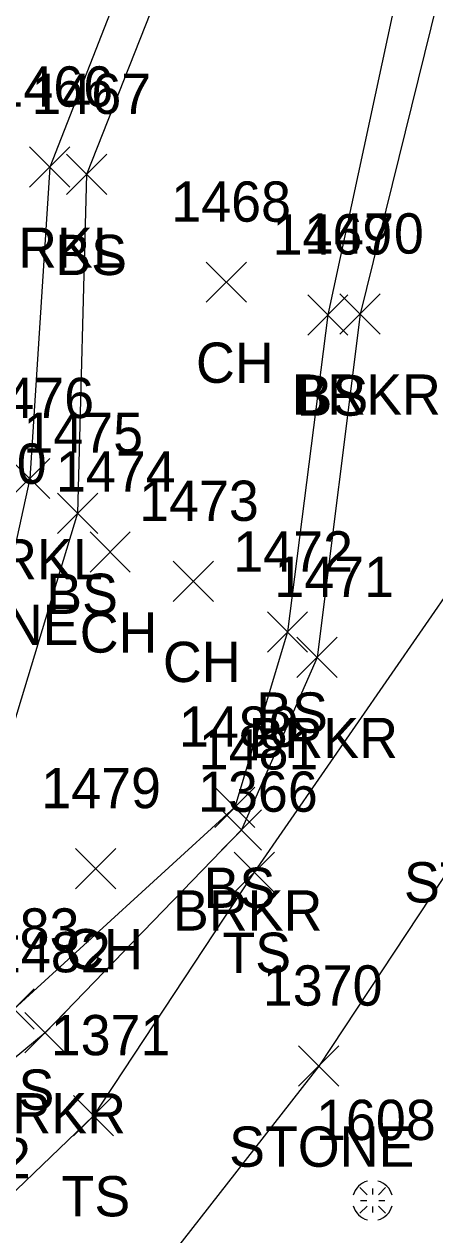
# Model space of a CAD drawing. Extents: x 1618262 to 1622220, y 273782 to 283685.
# Drawn here: x 1622120.3 to 1622140.8, y 282698.6 to 282758.7 of the extents above; entities that cross this region are included whole.
import ezdxf

# ---------------------------------------------------------------- set-up
doc = ezdxf.new("R2010")
doc.units = 0
for name, color, linetype in [('L_A', 7, 'Continuous'), ('L_I', 7, 'Continuous'), ('L_TIC', 7, 'Continuous'), ('LASF', 7, 'Continuous'), ('LAWE', 7, 'Continuous'), ('LELB', 7, 'Continuous'), ('M_I', 7, 'Continuous'), ('MMP', 7, 'Continuous')]:
    doc.layers.add(name, color=color, linetype=linetype)

msp = doc.modelspace()

# ---------------------------------------------------------------- linework, layer by layer
at = {"layer": 'L_TIC'}
for points in [[(1622120.615, 282750.647), (1622122.615, 282752.647)], [(1622122.615, 282750.647), (1622120.615, 282752.647)], [(1622122.45, 282750.287), (1622124.45, 282752.287)], [(1622124.45, 282750.287), (1622122.45, 282752.287)], [(1622129.397, 282744.935), (1622131.397, 282746.935)], [(1622131.397, 282744.935), (1622129.397, 282746.935)], [(1622134.441, 282743.305), (1622136.441, 282745.305)], [(1622136.441, 282743.305), (1622134.441, 282745.305)], [(1622136.038, 282743.352), (1622138.038, 282745.352)], [(1622138.038, 282743.352), (1622136.038, 282745.352)], [(1622119.62, 282735.185), (1622121.62, 282737.185)], [(1622121.62, 282735.185), (1622119.62, 282737.185)], [(1622122, 282733.461), (1622124, 282735.461)], [(1622124, 282733.461), (1622122, 282735.461)], [(1622123.619, 282731.54), (1622125.619, 282733.54)], [(1622125.619, 282731.54), (1622123.619, 282733.54)], [(1622127.751, 282730.08), (1622129.751, 282732.08)], [(1622129.751, 282730.08), (1622127.751, 282732.08)], [(1622132.432, 282727.566), (1622134.432, 282729.566)], [(1622134.432, 282727.566), (1622132.432, 282729.566)], [(1622133.906, 282726.302), (1622135.906, 282728.302)], [(1622135.906, 282726.302), (1622133.906, 282728.302)], [(1622129.817, 282718.866), (1622131.817, 282720.866)], [(1622131.817, 282718.866), (1622129.817, 282720.866)], [(1622130.147, 282717.739), (1622132.147, 282719.739)], [(1622132.147, 282717.739), (1622130.147, 282719.739)], [(1622122.897, 282715.817), (1622124.897, 282717.817)], [(1622124.897, 282715.817), (1622122.897, 282717.817)], [(1622130.784, 282715.638), (1622132.784, 282717.638)], [(1622132.784, 282715.638), (1622130.784, 282717.638)], [(1622118.838, 282708.844), (1622120.838, 282710.844)], [(1622120.838, 282708.844), (1622118.838, 282710.844)], [(1622120.386, 282707.668), (1622122.386, 282709.668)], [(1622122.386, 282707.668), (1622120.386, 282709.668)], [(1622133.988, 282706.013), (1622135.988, 282708.013)], [(1622135.988, 282706.013), (1622133.988, 282708.013)], [(1622122.793, 282703.55), (1622124.793, 282705.55)], [(1622124.793, 282703.55), (1622122.793, 282705.55)]]:
    msp.add_lwpolyline(points, dxfattribs=at)
at = {"layer": 'LASF'}
msp.add_lwpolyline([(1622145.163, 282735.978), (1622143.678, 282720.136), (1622134.988, 282707.013), (1622124.116, 282693.112), (1622102.742, 282693.292), (1622097.849, 282695.719), (1622096.809, 282706.041), (1622095.152, 282712.05), (1622094.742, 282720.999), (1622098.882, 282731.605), (1622115.268, 282742.964)], dxfattribs=at)
at = {"layer": 'LAWE'}
for points in [[(1622141.322, 282807.197), (1622130.736, 282774.943), (1622121.615, 282751.647), (1622120.62, 282736.185), (1622116.219, 282716.114), (1622112.294, 282712.254), (1622108.48, 282711.9), (1622107.608, 282715.746)], [(1622154.178, 282798.359), (1622145.032, 282776.682), (1622137.038, 282744.352), (1622134.906, 282727.302), (1622131.147, 282718.739), (1622121.386, 282708.668), (1622112.791, 282701.556), (1622107.385, 282699)]]:
    msp.add_lwpolyline(points, dxfattribs=at)
at = {"layer": 'LELB'}
for points in [[(1622143.151, 282805.581), (1622132.746, 282774.795), (1622123.45, 282751.287), (1622123, 282734.461), (1622117.166, 282715.275), (1622113.087, 282710.695), (1622107.286, 282710.498)], [(1622152.576, 282798.165), (1622142.264, 282776.026), (1622135.441, 282744.305), (1622133.432, 282728.566), (1622130.817, 282719.866), (1622119.838, 282709.844), (1622112.9, 282703.419), (1622107.406, 282701.551), (1622107.455, 282705.275), (1622107.333, 282706.567), (1622107.286, 282710.498), (1622106.865, 282715.564)], [(1622157.901, 282795.316), (1622151.518, 282778.21), (1622146.295, 282745.577), (1622145.163, 282735.978), (1622131.784, 282716.638), (1622123.793, 282704.55), (1622117.42, 282698.441), (1622102.742, 282693.292)]]:
    msp.add_lwpolyline(points, dxfattribs=at)
at = {"layer": 'MMP'}
for p, q in [((1622137.034, 282700.976), (1622137.387, 282700.623)), ((1622137.67, 282700.64), (1622137.67, 282700.94)), ((1622137.953, 282700.623), (1622138.306, 282700.976)), ((1622137.034, 282699.704), (1622137.387, 282700.057)), ((1622137.07, 282700.34), (1622137.37, 282700.34)), ((1622137.67, 282699.74), (1622137.67, 282700.04)), ((1622137.953, 282700.057), (1622138.306, 282699.704)), ((1622137.97, 282700.34), (1622138.27, 282700.34))]:
    msp.add_line(p, q, dxfattribs=at)
for start, end in [(105, 165), (15, 75), (195, 255), (285, 345)]:
    msp.add_arc((1622137.67, 282700.34), 1, start, end, dxfattribs=at)

# ---------------------------------------------------------------- texts
at = {"layer": 'L_A'}
for s, p in [('BRKL', (1622118.261, 282746.647)), ('BS', (1622121.891, 282746.287)), ('CH', (1622128.885, 282740.935)), ('BRKR', (1622133.629, 282739.352)), ('BS', (1622133.882, 282739.305)), ('BRKL', (1622117.266, 282731.185)), ('BS', (1622121.441, 282729.461)), ('STONE', (1622113.837, 282727.925)), ('CH', (1622123.107, 282727.54)), ('CH', (1622127.24, 282726.08)), ('BS', (1622131.873, 282723.566)), ('BRKR', (1622131.497, 282722.302)), ('BS', (1622129.258, 282714.866)), ('STONE', (1622139.221, 282715.136)), ('BRKR', (1622127.738, 282713.739)), ('CH', (1622122.385, 282711.817)), ('TS', (1622130.194, 282711.638)), ('BS', (1622118.279, 282704.844)), ('BRKR', (1622117.976, 282703.668)), ('STONE', (1622130.531, 282702.013)), ('TS', (1622122.202, 282699.55))]:
    msp.add_text(s, height=2, dxfattribs=at).set_placement(p)
at = {"layer": 'L_I'}
for s, p in [('1466', (1622118.82, 282754.647)), ('1467', (1622120.71, 282754.287)), ('1468', (1622127.657, 282748.935)), ('1469', (1622132.693, 282747.305)), ('1470', (1622134.259, 282747.352)), ('1476', (1622117.872, 282739.185)), ('1475', (1622120.307, 282737.461)), ('1520', (1622115.514, 282735.925)), ('1474', (1622121.927, 282735.54)), ('1473', (1622126.059, 282734.08)), ('1472', (1622130.739, 282731.566)), ('1471', (1622132.781, 282730.302)), ('1480', (1622128.038, 282722.866)), ('1481', (1622129.021, 282721.739)), ('1479', (1622121.196, 282719.817)), ('1366', (1622128.989, 282719.638)), ('1483', (1622117.145, 282712.844)), ('1482', (1622118.693, 282711.668)), ('1370', (1622132.208, 282710.013)), ('1371', (1622121.667, 282707.55)), ('1372', (1622114.727, 282701.441))]:
    msp.add_text(s, height=2, dxfattribs=at).set_placement(p)
at = {"layer": 'M_I'}
msp.add_text('1608', height=2, dxfattribs=at).set_placement((1622134.851, 282703.34))

doc.saveas('drawing.dxf')
